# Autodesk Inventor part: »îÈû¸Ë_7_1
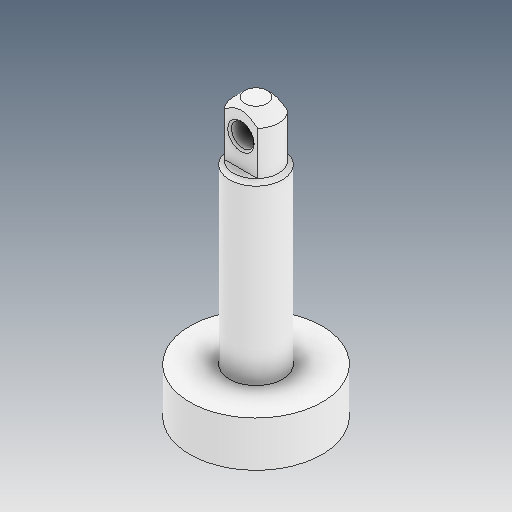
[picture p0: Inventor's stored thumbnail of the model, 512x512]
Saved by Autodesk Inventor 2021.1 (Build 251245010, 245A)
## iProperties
Created: 2021-05
Part Number: »îÈû¸Ë_7_1
Material: Ogólny
Document SubType Name: Modeling
Designer: user
Density: 1 g/cm^3
Appearance: Domyślna
Author: user
Revision Number: ÈÎºÎ
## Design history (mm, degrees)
feature "ÊäÈë1"
node "Bryła1"
